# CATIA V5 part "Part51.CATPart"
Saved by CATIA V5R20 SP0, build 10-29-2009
Part number: FA 042200-3
Revision: ANY
Definition: UNKNOWN
Nomenclature: FA 042200-3
Source: Unknown
Bounding box of the stored display mesh (mm): x 0 to 2, y -1.45 to 1.45, z -1.45 to 1.45
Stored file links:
  C:\Users\Utente\Desktop\IO LAVORO\3D X SITO CF\CUMSA\3D files FA\FA 042204-21\Part51.CATPart

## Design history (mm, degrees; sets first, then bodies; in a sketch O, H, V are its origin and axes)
Body1 "Revolución1" (main body)
  Solid1: solid without history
